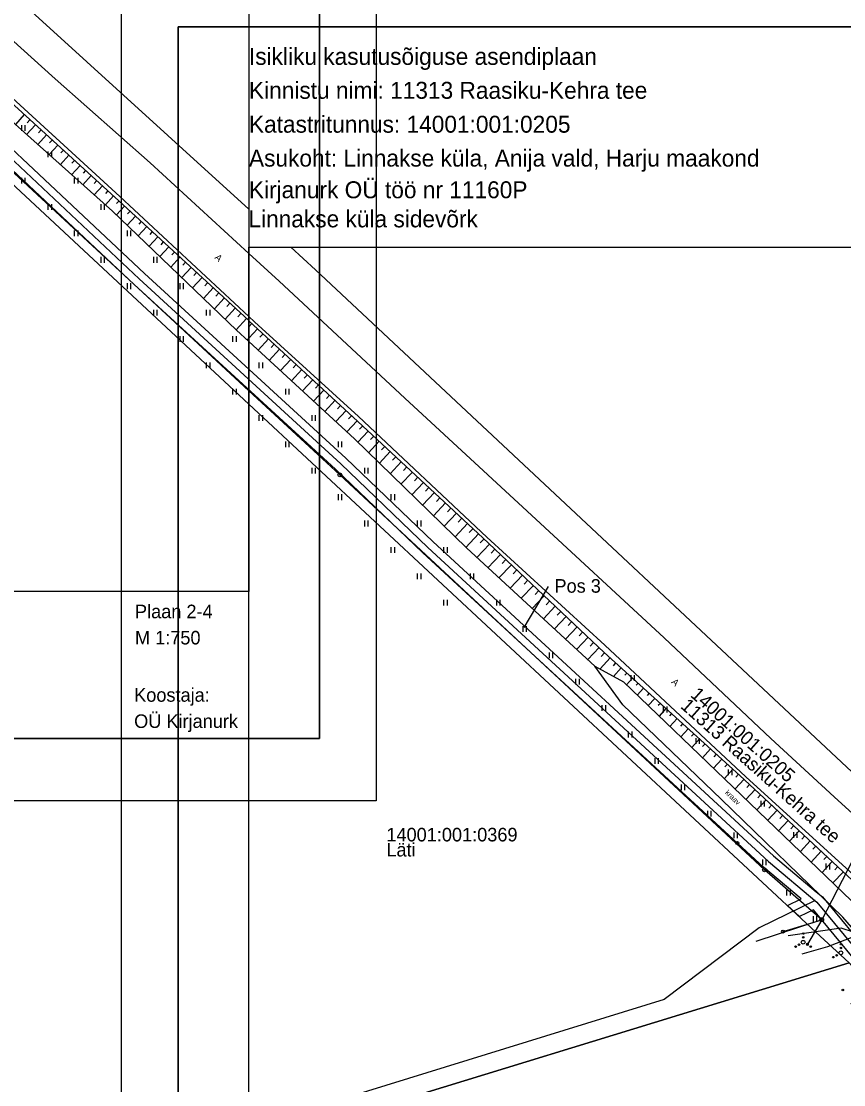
# Model space of a CAD drawing. Extents: x 567864 to 568657, y 6579839 to 6580994.
# Drawn here: x 568478.2 to 568587.3, y 6580268.5 to 6580409.7 of the extents above; entities that cross this region are included whole.
import ezdxf

# ---------------------------------------------------------------- set-up
doc = ezdxf.new("R2010")
doc.units = 0
for name, color, linetype in [('HALJASTUS', 7, 'Continuous'), ('KASUTUSALA', 7, 'Continuous'), ('KPOHULIIN', 7, 'Continuous'), ('PIIR', 7, 'Continuous'), ('POST', 7, 'Continuous'), ('PR_SIDE', 7, 'Continuous'), ('RELJEEF', 7, 'Continuous'), ('TEE', 7, 'Continuous'), ('VEEKOGU', 7, 'Continuous'), ('VORMISTUS_3', 7, 'Continuous'), ('VORMISTUS_4', 7, 'Continuous')]:
    doc.layers.add(name, color=color, linetype=linetype)

msp = doc.modelspace()

# ---------------------------------------------------------------- linework, layer by layer
at = {"layer": 'HALJASTUS'}
for p, q in [((568478.27, 6580395.88), (568478.27, 6580395.12)), ((568478.73, 6580395.88), (568478.73, 6580395.12)), ((568481.77, 6580392.38), (568481.77, 6580391.62)), ((568482.23, 6580392.38), (568482.23, 6580391.62)), ((568478.27, 6580388.88), (568478.27, 6580388.12)), ((568478.73, 6580388.88), (568478.73, 6580388.12)), ((568485.27, 6580388.88), (568485.27, 6580388.12)), ((568485.73, 6580388.88), (568485.73, 6580388.12)), ((568481.77, 6580385.38), (568481.77, 6580384.62)), ((568482.23, 6580385.38), (568482.23, 6580384.62)), ((568488.77, 6580385.38), (568488.77, 6580384.62)), ((568489.23, 6580385.38), (568489.23, 6580384.62)), ((568485.27, 6580381.88), (568485.27, 6580381.12)), ((568485.73, 6580381.88), (568485.73, 6580381.12)), ((568492.27, 6580381.88), (568492.27, 6580381.12)), ((568492.73, 6580381.88), (568492.73, 6580381.12)), ((568488.77, 6580378.38), (568488.77, 6580377.62)), ((568489.23, 6580378.38), (568489.23, 6580377.62)), ((568495.77, 6580378.38), (568495.77, 6580377.62)), ((568496.23, 6580378.38), (568496.23, 6580377.62)), ((568492.27, 6580374.88), (568492.27, 6580374.12)), ((568492.73, 6580374.88), (568492.73, 6580374.12)), ((568499.27, 6580374.88), (568499.27, 6580374.12)), ((568499.73, 6580374.88), (568499.73, 6580374.12)), ((568495.77, 6580371.38), (568495.77, 6580370.62)), ((568496.23, 6580371.38), (568496.23, 6580370.62)), ((568502.77, 6580371.38), (568502.77, 6580370.62)), ((568503.23, 6580371.38), (568503.23, 6580370.62)), ((568499.27, 6580367.88), (568499.27, 6580367.12)), ((568499.73, 6580367.88), (568499.73, 6580367.12)), ((568506.27, 6580367.88), (568506.27, 6580367.12)), ((568506.73, 6580367.88), (568506.73, 6580367.12)), ((568502.77, 6580364.38), (568502.77, 6580363.62)), ((568503.23, 6580364.38), (568503.23, 6580363.62)), ((568509.77, 6580364.38), (568509.77, 6580363.62)), ((568510.23, 6580364.38), (568510.23, 6580363.62)), ((568506.27, 6580360.88), (568506.27, 6580360.12)), ((568506.73, 6580360.88), (568506.73, 6580360.12)), ((568513.27, 6580360.88), (568513.27, 6580360.12)), ((568513.73, 6580360.88), (568513.73, 6580360.12)), ((568509.77, 6580357.38), (568509.77, 6580356.62)), ((568510.23, 6580357.38), (568510.23, 6580356.62)), ((568516.77, 6580357.38), (568516.77, 6580356.62)), ((568517.23, 6580357.38), (568517.23, 6580356.62)), ((568513.27, 6580353.88), (568513.27, 6580353.12)), ((568513.73, 6580353.88), (568513.73, 6580353.12)), ((568520.27, 6580353.88), (568520.27, 6580353.12)), ((568520.73, 6580353.88), (568520.73, 6580353.12)), ((568516.77, 6580350.38), (568516.77, 6580349.62)), ((568517.23, 6580350.38), (568517.23, 6580349.62)), ((568523.77, 6580350.38), (568523.77, 6580349.62)), ((568524.23, 6580350.38), (568524.23, 6580349.62)), ((568520.27, 6580346.88), (568520.27, 6580346.12)), ((568520.73, 6580346.88), (568520.73, 6580346.12)), ((568527.27, 6580346.88), (568527.27, 6580346.12)), ((568527.73, 6580346.88), (568527.73, 6580346.12)), ((568523.77, 6580343.38), (568523.77, 6580342.62)), ((568524.23, 6580343.38), (568524.23, 6580342.62)), ((568530.77, 6580343.38), (568530.77, 6580342.62)), ((568531.23, 6580343.38), (568531.23, 6580342.62)), ((568527.27, 6580339.88), (568527.27, 6580339.12)), ((568527.73, 6580339.88), (568527.73, 6580339.12)), ((568534.27, 6580339.88), (568534.27, 6580339.12)), ((568534.73, 6580339.88), (568534.73, 6580339.12)), ((568530.77, 6580336.38), (568530.77, 6580335.62)), ((568531.23, 6580336.38), (568531.23, 6580335.62)), ((568537.77, 6580336.38), (568537.77, 6580335.62)), ((568538.23, 6580336.38), (568538.23, 6580335.62)), ((568534.27, 6580332.88), (568534.27, 6580332.12)), ((568534.73, 6580332.88), (568534.73, 6580332.12)), ((568541.27, 6580332.88), (568541.27, 6580332.12)), ((568541.73, 6580332.88), (568541.73, 6580332.12)), ((568544.77, 6580329.38), (568544.77, 6580328.62)), ((568545.23, 6580329.38), (568545.23, 6580328.62)), ((568548.27, 6580325.88), (568548.27, 6580325.12)), ((568548.73, 6580325.88), (568548.73, 6580325.12)), ((568551.77, 6580322.38), (568551.77, 6580321.62)), ((568552.23, 6580322.38), (568552.23, 6580321.62)), ((568559.09, 6580322.87), (568559.09, 6580322.11)), ((568559.54, 6580322.87), (568559.54, 6580322.11)), ((568555.27, 6580318.88), (568555.27, 6580318.12)), ((568555.73, 6580318.88), (568555.73, 6580318.12)), ((568563.4, 6580318.7), (568563.4, 6580317.94)), ((568563.86, 6580318.7), (568563.86, 6580317.94)), ((568558.77, 6580315.38), (568558.77, 6580314.62)), ((568559.23, 6580315.38), (568559.23, 6580314.62)), ((568567.72, 6580314.53), (568567.72, 6580313.77)), ((568568.17, 6580314.53), (568568.17, 6580313.77)), ((568562.27, 6580311.88), (568562.27, 6580311.12)), ((568562.73, 6580311.88), (568562.73, 6580311.12)), ((568572.03, 6580310.36), (568572.03, 6580309.6)), ((568572.49, 6580310.36), (568572.49, 6580309.6)), ((568565.77, 6580308.38), (568565.77, 6580307.62)), ((568566.23, 6580308.38), (568566.23, 6580307.62)), ((568576.35, 6580306.2), (568576.35, 6580305.43)), ((568576.8, 6580306.2), (568576.8, 6580305.43)), ((568569.27, 6580304.88), (568569.27, 6580304.12)), ((568569.73, 6580304.88), (568569.73, 6580304.12)), ((568572.77, 6580302.01), (568572.77, 6580301.25)), ((568573.23, 6580302.01), (568573.23, 6580301.25)), ((568580.67, 6580302.03), (568580.67, 6580301.27)), ((568581.12, 6580302.03), (568581.12, 6580301.27)), ((568576.55, 6580298.42), (568576.55, 6580297.66)), ((568577.01, 6580298.42), (568577.01, 6580297.66)), ((568584.98, 6580297.86), (568584.98, 6580297.1)), ((568585.44, 6580297.86), (568585.44, 6580297.1)), ((568579.77, 6580294.38), (568579.77, 6580293.62)), ((568580.23, 6580294.38), (568580.23, 6580293.62)), ((568583.27, 6580290.88), (568583.27, 6580290.12)), ((568583.73, 6580290.88), (568583.73, 6580290.12))]:
    msp.add_line(p, q, dxfattribs=at)
msp.add_lwpolyline([(568588.28, 6580279.3), (568593.1, 6580281.62), (568599.12, 6580276.92), (568599.82, 6580277.57), (568592.22, 6580285.76), (568588.63, 6580288.77), (568587.02, 6580289.28), (568579.99, 6580288.26)], dxfattribs=at)
for centre, radius in [((568581.97, 6580288.58), 0.1), ((568580.97, 6580286.85), 0.1), ((568581.41, 6580287.1), 0.1), ((568581.97, 6580287.43), 0.25), ((568581.97, 6580288.08), 0.1), ((568582.54, 6580287.1), 0.1), ((568582.97, 6580286.85), 0.1), ((568586.97, 6580287.17), 0.1), ((568585.97, 6580285.45), 0.1), ((568586.4, 6580285.7), 0.1), ((568586.97, 6580286.02), 0.25), ((568586.97, 6580286.67), 0.1), ((568587.23, 6580281.09), 0.1)]:
    msp.add_circle(centre, radius, dxfattribs=at)
at = {"layer": 'KASUTUSALA'}
for points in [[(568461.42, 6580407.34), (568494.57, 6580376.2), (568521.29, 6580351.66), (568532.86, 6580340.57), (568578.04, 6580298.89), (568583.69, 6580294.14), (568584.34, 6580293.58), (568584.51, 6580293.44), (568597.53, 6580277.69), (568605.09, 6580268.66), (568620.33, 6580251.61)], [(568603.57, 6580267.35), (568595.99, 6580276.41), (568583.33, 6580291.74), (568581.46, 6580290.83), (568579.89, 6580292.29), (568581.72, 6580293.18), (568576.71, 6580297.39), (568531.49, 6580339.11), (568519.92, 6580350.2), (568493.21, 6580374.74), (568460.06, 6580405.87)]]:
    msp.add_lwpolyline(points, dxfattribs=at)
at = {"layer": 'KPOHULIIN'}
for points in [[(568508.43, 6580360.63), (568460.12, 6580405.36), (568402.88, 6580458.5), (568384.68, 6580466.25)], [(568584.43, 6580290.42), (568576.83, 6580297.04), (568520.5, 6580349.45), (568508.43, 6580360.63)], [(568591.82, 6580304.68), (568584.43, 6580290.42), (568575.69, 6580287.52)]]:
    msp.add_lwpolyline(points, dxfattribs=at)
at = {"layer": 'PIIR'}
for points in [[(568391.3, 6580491.46), (568392.03, 6580490.79), (568429.88, 6580456.3), (568437.22, 6580449.61), (568476.19, 6580414.1), (568508.43, 6580384.73)], [(568508.43, 6580358.86), (568387.31, 6580471.69), (568384.68, 6580474.14)], [(568384.68, 6580470.15), (568387.31, 6580471.69), (568508.43, 6580358.86)], [(568508.43, 6580384.73), (568476.19, 6580414.1), (568508.43, 6580441.35)], [(568513.99, 6580379.67), (568517.27, 6580376.68), (568603.64, 6580295.78), (568625.46, 6580274.99), (568632.18, 6580269.03)], [(568632.18, 6580269.03), (568625.46, 6580274.99), (568603.64, 6580295.78), (568517.27, 6580376.68), (568513.99, 6580379.67)], [(568628.53, 6580222.17), (568629.55, 6580235.74), (568618.77, 6580250.35), (568588.05, 6580284.69), (568583.66, 6580288.78), (568508.43, 6580358.86)], [(568508.43, 6580358.86), (568583.66, 6580288.78), (568588.05, 6580284.69), (568508.43, 6580260.29)], [(568508.43, 6580260.29), (568588.05, 6580284.69), (568618.77, 6580250.35), (568629.55, 6580235.74), (568628.53, 6580222.17)]]:
    msp.add_lwpolyline(points, dxfattribs=at)
at = {"layer": 'POST'}
for points in [[(568573.25, 6580300.58), (568576.83, 6580297.04)], [(568579.3, 6580288.85), (568584.43, 6580290.42)], [(568584.43, 6580290.42), (568582.52, 6580287.18)]]:
    msp.add_lwpolyline(points, dxfattribs=at)
for centre, radius in [((568520.5, 6580349.45), 0.25), ((568520.5, 6580349.45), 0.0234), ((568573.25, 6580300.58), 0.2), ((568576.83, 6580297.04), 0.25), ((568576.83, 6580297.04), 0.0234), ((568584.43, 6580290.42), 0.25), ((568584.43, 6580290.42), 0.0234), ((568579.3, 6580288.85), 0.2), ((568582.52, 6580287.18), 0.125), ((568582.52, 6580287.18), 0.105), ((568582.52, 6580287.18), 0.0851), ((568582.52, 6580287.18), 0.0651), ((568582.52, 6580287.18), 0.0451), ((568582.52, 6580287.18), 0.0251), ((568582.52, 6580287.18), 0.00511)]:
    msp.add_circle(centre, radius, dxfattribs=at)
at = {"layer": 'PR_SIDE'}
for points in [[(568418.48, 6580444.49), (568438.25, 6580426.85), (568460.74, 6580406.61), (568493.89, 6580375.47), (568520.61, 6580350.93), (568532.18, 6580339.84), (568577.38, 6580298.14), (568583.8, 6580292.74), (568596.76, 6580277.05), (568604.33, 6580268.01), (568619.55, 6580250.98), (568628.57, 6580238.42), (568627.43, 6580222.17)], [(568583.54, 6580292.96), (568576.12, 6580289.35), (568563.54, 6580279.82), (568508.43, 6580262.79)]]:
    msp.add_lwpolyline(points, dxfattribs=at)
at = {"layer": 'RELJEEF'}
for p, q in [((568478.64, 6580397.27), (568477.45, 6580395.96)), ((568480.12, 6580395.92), (568478.94, 6580394.63)), ((568479.38, 6580396.59), (568479.03, 6580396.2)), ((568481.6, 6580394.57), (568480.44, 6580393.3)), ((568480.86, 6580395.25), (568480.51, 6580394.86)), ((568483.08, 6580393.22), (568481.93, 6580391.96)), ((568482.34, 6580393.9), (568481.99, 6580393.52)), ((568484.56, 6580391.88), (568483.42, 6580390.63)), ((568483.82, 6580392.55), (568483.47, 6580392.18)), ((568486.03, 6580390.53), (568484.92, 6580389.3)), ((568485.29, 6580391.2), (568484.96, 6580390.83)), ((568487.51, 6580389.18), (568486.41, 6580387.97)), ((568486.77, 6580389.86), (568486.44, 6580389.49)), ((568488.25, 6580388.51), (568487.92, 6580388.15)), ((568488.99, 6580387.83), (568487.9, 6580386.64)), ((568489.73, 6580387.16), (568489.4, 6580386.8)), ((568490.47, 6580386.49), (568489.39, 6580385.31)), ((568491.21, 6580385.81), (568490.88, 6580385.46)), ((568491.94, 6580385.13), (568490.86, 6580383.97)), ((568492.67, 6580384.45), (568492.35, 6580384.1)), ((568493.41, 6580383.78), (568492.3, 6580382.58)), ((568494.14, 6580383.1), (568493.81, 6580382.73)), ((568494.88, 6580382.42), (568493.75, 6580381.19)), ((568495.61, 6580381.74), (568495.27, 6580381.37)), ((568496.35, 6580381.06), (568495.19, 6580379.81)), ((568497.08, 6580380.38), (568496.73, 6580380)), ((568497.82, 6580379.71), (568496.63, 6580378.42)), ((568498.55, 6580379.03), (568498.19, 6580378.64)), ((568499.29, 6580378.35), (568498.08, 6580377.04)), ((568500.02, 6580377.67), (568499.65, 6580377.27)), ((568500.76, 6580376.99), (568499.52, 6580375.65)), ((568501.49, 6580376.31), (568501.12, 6580375.91)), ((568502.23, 6580375.64), (568500.96, 6580374.27)), ((568502.96, 6580374.96), (568502.58, 6580374.54)), ((568503.7, 6580374.28), (568502.4, 6580372.88)), ((568504.43, 6580373.6), (568504.04, 6580373.18)), ((568505.16, 6580372.92), (568503.85, 6580371.49)), ((568506.63, 6580371.57), (568505.29, 6580370.11)), ((568505.9, 6580372.24), (568505.5, 6580371.81)), ((568508.1, 6580370.21), (568506.73, 6580368.72)), ((568507.37, 6580370.89), (568506.96, 6580370.45)), ((568508.84, 6580369.53), (568508.43, 6580369.09)), ((568508.43, 6580369.09), (568508.43, 6580369.08)), ((568509.57, 6580368.85), (568508.43, 6580367.61)), ((568508.43, 6580367.61), (568508.2, 6580367.36)), ((568511.04, 6580367.5), (568509.67, 6580366.01)), ((568510.31, 6580368.17), (568509.9, 6580367.73)), ((568512.51, 6580366.14), (568511.14, 6580364.65)), ((568511.78, 6580366.82), (568511.37, 6580366.37)), ((568513.98, 6580364.78), (568512.61, 6580363.3)), ((568513.25, 6580365.46), (568512.84, 6580365.02)), ((568515.45, 6580363.43), (568514.08, 6580361.94)), ((568514.72, 6580364.1), (568514.31, 6580363.66)), ((568516.92, 6580362.07), (568515.55, 6580360.59)), ((568516.19, 6580362.75), (568515.78, 6580362.3)), ((568518.39, 6580360.71), (568517.02, 6580359.23)), ((568517.66, 6580361.39), (568517.25, 6580360.95)), ((568519.86, 6580359.36), (568518.49, 6580357.87)), ((568519.13, 6580360.04), (568518.72, 6580359.59)), ((568521.33, 6580358), (568519.96, 6580356.52)), ((568520.6, 6580358.68), (568520.19, 6580358.23)), ((568522.8, 6580356.64), (568521.43, 6580355.16)), ((568522.07, 6580357.32), (568521.66, 6580356.88)), ((568524.26, 6580355.28), (568522.88, 6580353.8)), ((568523.53, 6580355.96), (568523.12, 6580355.52)), ((568525.73, 6580353.92), (568524.32, 6580352.4)), ((568525, 6580354.6), (568524.58, 6580354.15)), ((568526.46, 6580353.24), (568526.03, 6580352.78)), ((568527.19, 6580352.55), (568525.75, 6580351.01)), ((568527.92, 6580351.87), (568527.49, 6580351.4)), ((568528.65, 6580351.19), (568527.18, 6580349.61)), ((568529.39, 6580350.51), (568528.94, 6580350.03)), ((568530.12, 6580349.83), (568528.61, 6580348.22)), ((568530.85, 6580349.15), (568530.39, 6580348.66)), ((568531.58, 6580348.46), (568530.05, 6580346.82)), ((568532.31, 6580347.78), (568531.85, 6580347.28)), ((568533.04, 6580347.1), (568531.48, 6580345.42)), ((568533.78, 6580346.42), (568533.3, 6580345.91)), ((568534.51, 6580345.74), (568532.91, 6580344.03)), ((568535.24, 6580345.06), (568534.76, 6580344.54)), ((568535.97, 6580344.37), (568534.34, 6580342.63)), ((568536.7, 6580343.69), (568536.21, 6580343.16)), ((568537.43, 6580343.01), (568535.78, 6580341.23)), ((568538.17, 6580342.33), (568537.66, 6580341.79)), ((568538.9, 6580341.65), (568537.21, 6580339.84)), ((568539.63, 6580340.96), (568539.12, 6580340.43)), ((568540.35, 6580340.28), (568538.67, 6580338.49)), ((568541.08, 6580339.59), (568540.58, 6580339.06)), ((568541.81, 6580338.9), (568540.14, 6580337.14)), ((568542.53, 6580338.22), (568542.04, 6580337.69)), ((568543.26, 6580337.53), (568541.61, 6580335.78)), ((568543.99, 6580336.84), (568543.49, 6580336.32)), ((568544.71, 6580336.15), (568543.08, 6580334.43)), ((568545.44, 6580335.47), (568544.95, 6580334.95)), ((568546.17, 6580334.78), (568544.56, 6580333.08)), ((568546.89, 6580334.09), (568546.41, 6580333.58)), ((568547.62, 6580333.4), (568546.03, 6580331.72)), ((568548.34, 6580332.72), (568547.87, 6580332.22)), ((568549.07, 6580332.03), (568547.5, 6580330.37)), ((568550.52, 6580330.66), (568548.97, 6580329.02)), ((568549.8, 6580331.34), (568549.33, 6580330.85)), ((568551.98, 6580329.28), (568550.45, 6580327.66)), ((568551.25, 6580329.97), (568550.79, 6580329.48)), ((568553.43, 6580327.91), (568551.92, 6580326.31)), ((568552.7, 6580328.59), (568552.25, 6580328.11)), ((568554.88, 6580326.53), (568553.39, 6580324.96)), ((568554.16, 6580327.22), (568553.71, 6580326.74)), ((568556.35, 6580325.18), (568555.02, 6580323.71)), ((568555.61, 6580325.85), (568555.18, 6580325.37)), ((568557.09, 6580324.5), (568556.74, 6580324.12)), ((568557.83, 6580323.83), (568556.82, 6580322.71)), ((568558.57, 6580323.16), (568558.32, 6580322.88)), ((568559.31, 6580322.49), (568558.52, 6580321.61)), ((568560.06, 6580321.82), (568559.81, 6580321.55)), ((568560.8, 6580321.14), (568559.96, 6580320.22)), ((568561.54, 6580320.47), (568561.28, 6580320.19)), ((568562.28, 6580319.8), (568561.4, 6580318.84)), ((568563.02, 6580319.13), (568562.75, 6580318.83)), ((568563.76, 6580318.46), (568562.85, 6580317.45)), ((568564.5, 6580317.79), (568564.22, 6580317.48)), ((568565.24, 6580317.11), (568564.29, 6580316.06)), ((568565.98, 6580316.44), (568565.69, 6580316.12)), ((568566.72, 6580315.77), (568565.73, 6580314.68)), ((568567.46, 6580315.1), (568567.16, 6580314.77)), ((568568.2, 6580314.43), (568567.18, 6580313.29)), ((568568.95, 6580313.76), (568568.63, 6580313.41)), ((568569.69, 6580313.08), (568568.62, 6580311.91)), ((568570.43, 6580312.41), (568570.1, 6580312.05)), ((568571.17, 6580311.74), (568570.06, 6580310.52)), ((568571.91, 6580311.07), (568571.57, 6580310.7)), ((568572.65, 6580310.4), (568571.51, 6580309.14)), ((568573.39, 6580309.73), (568573.04, 6580309.34)), ((568574.12, 6580309.05), (568572.93, 6580307.77)), ((568574.86, 6580308.37), (568574.5, 6580307.98)), ((568575.59, 6580307.68), (568574.38, 6580306.38)), ((568576.32, 6580307), (568575.95, 6580306.61)), ((568577.05, 6580306.32), (568575.82, 6580305)), ((568577.78, 6580305.64), (568577.41, 6580305.24)), ((568578.51, 6580304.96), (568577.26, 6580303.61)), ((568579.25, 6580304.28), (568578.87, 6580303.87)), ((568579.98, 6580303.59), (568578.7, 6580302.22)), ((568580.71, 6580302.91), (568580.32, 6580302.5)), ((568581.44, 6580302.23), (568580.14, 6580300.84)), ((568582.17, 6580301.55), (568581.78, 6580301.13)), ((568582.91, 6580300.87), (568581.59, 6580299.45)), ((568583.64, 6580300.19), (568583.24, 6580299.76)), ((568584.37, 6580299.5), (568583.03, 6580298.07)), ((568585.1, 6580298.82), (568584.7, 6580298.39)), ((568585.83, 6580298.14), (568584.47, 6580296.68)), ((568587.3, 6580296.78), (568585.91, 6580295.3)), ((568586.56, 6580297.46), (568586.15, 6580297.02))]:
    msp.add_line(p, q, dxfattribs=at)
for points in [[(568508.43, 6580369.91), (568508.36, 6580369.97), (568491.19, 6580385.82), (568473.19, 6580402.25), (568454, 6580419.43), (568439.25, 6580432.58), (568424.48, 6580446.12), (568410.28, 6580459.77), (568392.73, 6580475.54), (568387.59, 6580476.46), (568384.68, 6580475.8)], [(568508.43, 6580367.15), (568506.78, 6580368.67), (568490.34, 6580384.47), (568471.54, 6580401.22), (568453.41, 6580417.78), (568436.55, 6580429.77), (568424.43, 6580443.61), (568407.63, 6580458.36), (568391.91, 6580472.02), (568385.01, 6580473.1), (568384.68, 6580472.9)], [(568605.01, 6580280.6), (568596.41, 6580288.68), (568591.09, 6580293.25), (568573.56, 6580309.57), (568555.55, 6580325.9), (568539.48, 6580341.11), (568522.9, 6580356.55), (568508.43, 6580369.91)], [(568554.33, 6580324.09), (568537.34, 6580339.71), (568522.44, 6580354.23), (568508.43, 6580367.15)]]:
    msp.add_lwpolyline(points, dxfattribs=at)
at = {"layer": 'TEE'}
for points in [[(568508.43, 6580378.85), (568495.33, 6580390.85), (568482.75, 6580402.03), (568475.41, 6580408.62), (568468.57, 6580415.05), (568463.22, 6580419.85), (568458.45, 6580424.26), (568444.27, 6580436.5), (568431.32, 6580448.81), (568430.18, 6580450.35), (568426.97, 6580453.17), (568425.25, 6580454.08), (568411.89, 6580467.48), (568409.94, 6580469.27), (568402.86, 6580475.84), (568393.71, 6580484.18), (568385.88, 6580491.46)], [(568384.68, 6580477), (568386.1, 6580477.37), (568389.56, 6580477.71), (568393.35, 6580475.97), (568411.04, 6580459.97), (568424.79, 6580447.11), (568440.15, 6580432.91), (568454.13, 6580420.18), (568473.8, 6580402.4), (568491.3, 6580386.42), (568508.43, 6580370.47)], [(568632.18, 6580259.41), (568631.27, 6580261.38), (568627.21, 6580267.03), (568621.95, 6580273.22), (568615.8, 6580279.31), (568608.79, 6580285.93), (568598.88, 6580295.04), (568586.08, 6580306.74), (568577.68, 6580314.48), (568563.53, 6580327.85), (568545.36, 6580344.62), (568529.11, 6580359.65), (568512.43, 6580375.18), (568508.43, 6580378.85)], [(568508.43, 6580370.47), (568509.17, 6580369.79), (568522.98, 6580357.19), (568540.01, 6580341.2), (568555.65, 6580326.86), (568574.36, 6580309.39), (568592.09, 6580293.25), (568597.76, 6580288.15), (568605.72, 6580280.8), (568616.48, 6580270.4), (568621.57, 6580264.87), (568624.14, 6580261.44), (568626.74, 6580257.05), (568628.43, 6580254.18), (568629.48, 6580251.71), (568629.92, 6580249.85), (568631.52, 6580242.99), (568632.18, 6580237.44)]]:
    msp.add_lwpolyline(points, dxfattribs=at)
at = {"layer": 'VEEKOGU'}
msp.add_lwpolyline([(568581.85, 6580285.88), (568585.24, 6580286.87), (568589.25, 6580288.4), (568587.21, 6580290.75), (568571.08, 6580306.43), (568558.05, 6580318.95), (568554.33, 6580324.09), (568558.12, 6580321.99), (568572.68, 6580308.01), (568589.49, 6580291.86), (568595.68, 6580287.17), (568603.87, 6580279.55), (568610.43, 6580274.47), (568615.96, 6580269.02), (568621.24, 6580264.81)], dxfattribs=at)
at = {"layer": 'VORMISTUS_3'}
for points in [[(568367.8, 6580528.96), (568525.3, 6580528.96), (568525.3, 6580306.21), (568367.8, 6580306.21)], [(568375.3, 6580314.46), (568517.8, 6580314.46), (568517.8, 6580520.71), (568375.3, 6580520.71)], [(568375.3, 6580520.71), (568517.8, 6580520.71), (568517.8, 6580314.46), (568375.3, 6580314.46)], [(568508.43, 6580333.96), (568384.68, 6580333.96), (568384.68, 6580491.46), (568508.43, 6580491.46)]]:
    msp.add_lwpolyline(points, close=True, dxfattribs=at)
at = {"layer": 'VORMISTUS_4'}
msp.add_line((568544.93, 6580329.2), (568548.17, 6580334.63), dxfattribs=at)
for points in [[(568491.55, 6580417.17), (568649.05, 6580417.17), (568649.05, 6580194.42), (568491.55, 6580194.42)], [(568499.05, 6580202.67), (568641.55, 6580202.67), (568641.55, 6580408.92), (568499.05, 6580408.92)], [(568499.05, 6580408.92), (568641.55, 6580408.92), (568641.55, 6580202.67), (568499.05, 6580202.67)], [(568632.18, 6580222.17), (568508.43, 6580222.17), (568508.43, 6580379.67), (568632.18, 6580379.67)]]:
    msp.add_lwpolyline(points, close=True, dxfattribs=at)

# ---------------------------------------------------------------- texts
at = {"layer": 'PIIR'}
for s, p in [('14001:001:0205', (568566.91, 6580320.11)), ('11313 Raasiku-Kehra tee', (568565.58, 6580318.62))]:
    msp.add_text(s, height=1.8, rotation=318.2331, dxfattribs=at).set_placement(p)
for s, p in [('14001:001:0369', (568526.67, 6580300.81)), ('Läti', (568526.67, 6580298.81))]:
    msp.add_text(s, height=1.8, dxfattribs=at).set_placement(p)
at = {"layer": 'TEE'}
for p in [(568503.82, 6580378.23), (568564.41, 6580321.89)]:
    msp.add_text('A', height=0.9, rotation=315.2576, dxfattribs=at).set_placement(p)
at = {"layer": 'VEEKOGU'}
msp.add_text('kraav', height=0.7, rotation=316.1326, dxfattribs=at).set_placement((568571.54, 6580307.21))
at = {"layer": 'VORMISTUS_3'}
for s, p in [('Plaan 2-4', (568493.32, 6580330.43)), ('M 1:750', (568493.32, 6580326.95)), ('Koostaja:', (568493.21, 6580319.35)), ('OÜ Kirjanurk', (568493.21, 6580315.87))]:
    msp.add_text(s, height=1.8, dxfattribs=at).set_placement(p)
at = {"layer": 'VORMISTUS_4'}
for s, height, p in [('Isikliku kasutusõiguse asendiplaan', 2.25, (568508.44, 6580403.87)), ('Kinnistu nimi: 11313 Raasiku-Kehra tee', 2.25, (568508.44, 6580399.37)), ('Katastritunnus: 14001:001:0205', 2.25, (568508.44, 6580394.87)), ('Asukoht: Linnakse küla, Anija vald, Harju maakond', 2.25, (568508.44, 6580390.37)), ('Pos 3', 1.8, (568548.97, 6580333.82))]:
    msp.add_text(s, height=height, dxfattribs=at).set_placement(p)
for s, p in [('Kirjanurk OÜ töö nr 11160P', (568508.43, 6580386.17)), ('Linnakse küla sidevõrk', (568508.37, 6580382.31))]:
    msp.add_text(s, height=2.25, rotation=360, dxfattribs=at).set_placement(p)

doc.saveas('drawing.dxf')
